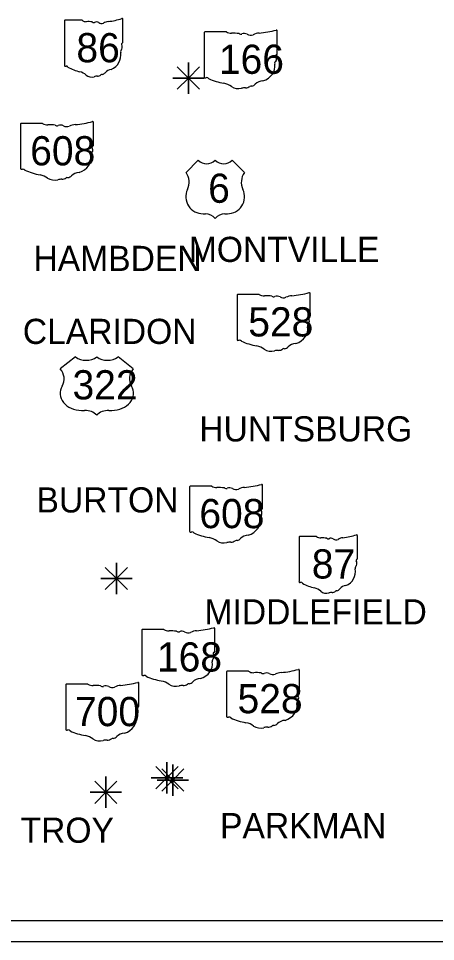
# Model space of a CAD drawing. Extents: x -1 to 48.3, y -9.3 to 22.
# Drawn here: x 5.63 to 7.62, y 14 to 18.402 of the extents above; entities that cross this region are included whole.
import ezdxf

# ---------------------------------------------------------------- set-up
doc = ezdxf.new("R2010")
doc.units = 0
for name, color, linetype in [('GM_X_County', 7, 'Continuous'), ('GM_X_County_Road', 7, 'Continuous'), ('GM_X_Minor_River_Text', 7, 'Continuous'), ('GM_X_Township', 7, 'Continuous')]:
    doc.layers.add(name, color=color, linetype=linetype)

msp = doc.modelspace()

# ---------------------------------------------------------------- linework, layer by layer
at = {"layer": 'GM_X_County'}
for p, q in [((2.1, 14.1), (8.9, 14.1)), ((2, 14), (9, 14))]:
    msp.add_line(p, q, dxfattribs=at)
at = {"layer": 'GM_X_County_Road'}
for p, q in [((5.8491, 18.3892), (5.8491, 18.1778)), ((5.9333, 18.3928), (5.8518, 18.3928)), ((6.1275, 18.2875), (6.1275, 18.398)), ((6.5168, 18.334), (6.5168, 18.1226)), ((6.6222, 18.3376), (6.5202, 18.3376)), ((6.8649, 18.2323), (6.8649, 18.3428)), ((6.1275, 18.2875), (6.1275, 18.2875)), ((6.8648, 18.2323), (6.8649, 18.2323)), ((5.6396, 17.8975), (5.6396, 17.6862)), ((5.745, 17.9011), (5.643, 17.9011)), ((5.9877, 17.7958), (5.9877, 17.9064)), ((5.9876, 17.7959), (5.9877, 17.7958)), ((6.6735, 17.0817), (6.6735, 16.8704)), ((6.7788, 17.0854), (6.6769, 17.0854)), ((7.0215, 16.9801), (7.0215, 17.0906)), ((7.0215, 16.9801), (7.0215, 16.9801)), ((6.4468, 16.1676), (6.4468, 15.9562)), ((6.5521, 16.1712), (6.4502, 16.1712)), ((6.7948, 16.0659), (6.7948, 16.1764)), ((6.7948, 16.0659), (6.7948, 16.0659)), ((7.2472, 15.8258), (7.2472, 15.9363)), ((6.9688, 15.9274), (6.9688, 15.7161)), ((7.0531, 15.9311), (6.9715, 15.9311)), ((7.2472, 15.8258), (7.2472, 15.8258)), ((6.2184, 15.4839), (6.2184, 15.2726)), ((6.3237, 15.4875), (6.2218, 15.4875)), ((6.5664, 15.3822), (6.5664, 15.4928)), ((6.5664, 15.3823), (6.5664, 15.3822)), ((6.6224, 15.285), (6.6224, 15.0737)), ((6.7277, 15.2886), (6.6258, 15.2886)), ((6.9704, 15.1833), (6.9704, 15.2939)), ((6.204, 15.1217), (6.204, 15.2323)), ((5.8559, 15.2234), (5.8559, 15.0121)), ((5.9613, 15.227), (5.8593, 15.227)), ((6.9704, 15.1834), (6.9704, 15.1833)), ((6.2039, 15.1217), (6.204, 15.1217))]:
    msp.add_line(p, q, dxfattribs=at)
for centre, radius, start, end in [((6.0283, 18.6809), 0.2953, 275.8445, 288.9065), ((6.1244, 18.3985), 0.0031, 351.8621, 97.738), ((5.8523, 18.3896), 0.00323, 98.1301, 188.1301), ((5.9528, 18.4173), 0.0313, 231.6195, 271.1119), ((5.9631, 18.2742), 0.1123, 80.4867, 94.9883), ((5.9886, 18.3907), 0.00903, 219.7921, 297.1024), ((6.0019, 18.3663), 0.0188, 54.4667, 119.1411), ((6.0261, 18.3998), 0.0226, 233.8562, 294.8282), ((6.066, 18.3283), 0.0594, 97.3462, 120.7689), ((6.1268, 18.2794), 0.0048, 107.944, 210.337), ((6.0963, 18.2654), 0.0288, 340.033, 23.6496), ((6.1242, 18.2871), 0.00332, 289.6038, 7.7341), ((6.0449, 18.2272), 0.0739, 292.3089, 8.9858), ((6.1386, 18.2412), 0.021, 136.8065, 186.9296), ((5.8523, 18.1774), 0.00325, 171.9584, 258.3066), ((5.8528, 18.199), 0.0248, 267.339, 280.6039), ((5.8579, 18.1656), 0.00895, 29.7484, 93.2717), ((5.9709, 18.3555), 0.2132, 240.4129, 257.1985), ((5.9073, 18.0829), 0.0667, 47.1842, 75.836), ((6.0275, 18.1283), 0.00635, 65.7517, 132.6484), ((6.0247, 18.1574), 0.0239, 282.8732, 323.2771), ((6.076, 18.1185), 0.0404, 94.4031, 142.5768), ((5.9795, 18.1646), 0.0423, 230.7004, 286.2918), ((6.004, 18.0915), 0.0348, 85.6951, 111.2099), ((6.007, 18.1488), 0.0226, 268.777, 315.5493), ((7.1481, 16.2192), 0.2953, 275.8445, 288.9065), ((7.2441, 15.9368), 0.0031, 351.8621, 97.738), ((6.972, 15.9279), 0.00323, 98.1301, 188.1301), ((7.0725, 15.9556), 0.0313, 231.6195, 271.1119), ((7.0829, 15.8124), 0.1123, 80.4867, 94.9883), ((7.1084, 15.929), 0.00903, 219.7921, 297.1024), ((7.1216, 15.9046), 0.0188, 54.4667, 119.1411), ((7.1458, 15.9381), 0.0226, 233.8562, 294.8282), ((7.1857, 15.8665), 0.0594, 97.3462, 120.7689), ((7.2465, 15.8176), 0.0048, 107.944, 210.337), ((7.216, 15.8037), 0.0288, 340.033, 23.6496), ((7.2439, 15.8253), 0.00332, 289.6038, 7.7341), ((7.1646, 15.7654), 0.0739, 292.3089, 8.9858), ((7.2583, 15.7795), 0.021, 136.8065, 186.9296), ((6.972, 15.7156), 0.00325, 171.9584, 258.3066), ((6.9725, 15.7373), 0.0248, 267.339, 280.6039), ((6.9776, 15.7039), 0.00895, 29.7484, 93.2717), ((7.0906, 15.8938), 0.2132, 240.4129, 257.1985), ((7.0271, 15.6212), 0.0667, 47.1842, 75.836), ((7.0992, 15.7029), 0.0423, 230.7004, 286.2918), ((7.1268, 15.687), 0.0226, 268.777, 315.5493), ((7.1472, 15.6666), 0.00635, 65.7517, 132.6484), ((7.1445, 15.6956), 0.0239, 282.8732, 323.2771), ((7.1957, 15.6568), 0.0404, 94.4031, 142.5768), ((7.1237, 15.6298), 0.0348, 85.6951, 111.2099)]:
    msp.add_arc(centre, radius, start, end, dxfattribs=at)
for centre, major_axis, start_param, end_param in [((6.5208, 18.3344), (0.00403, 0), 1.712693, 3.28349), ((6.6464, 18.3621), (0.0391, 0), 4.042523, 4.731795), ((6.6594, 18.2189), (0.1404, 0), 1.404758, 1.657858), ((6.6913, 18.3355), (0.0113, 0), 3.836095, 5.185415), ((6.7078, 18.3111), (0.0235, 0), 0.950623, 2.079405), ((6.7381, 18.3446), (0.0282, 0), 4.081561, 5.145723), ((6.788, 18.273), (0.0743, 0), 1.699011, 2.107814), ((6.7409, 18.6257), (0.3691, 0), 4.814394, 5.042369), ((6.861, 18.3433), (0.00387, 0), 6.141152, 7.989035), ((6.864, 18.2242), (0.006, 0), 1.883978, 3.671073), ((6.8607, 18.2318), (0.00415, 0), 5.05454, 6.418171), ((6.7616, 18.172), (0.0923, 0), 5.101752, 6.440018), ((6.8787, 18.186), (0.0262, 0), 2.387724, 3.262537), ((6.8258, 18.2102), (0.036, 0), 5.934695, 6.695948), ((6.5208, 18.1222), (0.00407, 0), 3.00124, 4.508301), ((6.5215, 18.1438), (0.031, 0), 4.665946, 4.897461), ((6.5278, 18.1104), (0.0112, 0), 0.519207, 1.627899), ((6.6691, 18.3003), (0.2665, 0), 4.195997, 4.488961), ((6.5897, 18.0277), (0.0834, 0), 0.823519, 1.323587), ((6.8005, 18.0633), (0.0506, 0), 1.647645, 2.488434), ((6.6799, 18.1094), (0.0529, 0), 4.026481, 4.996735), ((6.7104, 18.0363), (0.0435, 0), 1.495662, 1.94098), ((6.7143, 18.0936), (0.0282, 0), 4.691044, 5.507374), ((6.7398, 18.0731), (0.00794, 0), 1.147584, 2.315152), ((6.7364, 18.1021), (0.0298, 0), 4.937069, 5.64225), ((5.6436, 17.8979), (0.00403, 0), 1.712693, 3.28349), ((5.7692, 17.9257), (0.0391, 0), 4.042523, 4.731795), ((5.7822, 17.7825), (0.1404, 0), 1.404758, 1.657858), ((5.8141, 17.899), (0.0113, 0), 3.836095, 5.185415), ((5.8306, 17.8746), (0.0235, 0), 0.950623, 2.079405), ((5.8609, 17.9081), (0.0282, 0), 4.081561, 5.145723), ((5.9108, 17.8366), (0.0743, 0), 1.699011, 2.107814), ((5.8637, 18.1892), (0.3691, 0), 4.814394, 5.042369), ((5.9838, 17.9068), (0.00387, 0), 6.141152, 7.989035), ((5.9868, 17.7877), (0.006, 0), 1.883978, 3.671073), ((5.9486, 17.7737), (0.036, 0), 5.934695, 6.695948), ((5.9835, 17.7954), (0.00415, 0), 5.05454, 6.418171), ((5.8844, 17.7355), (0.0923, 0), 5.101752, 6.440018), ((6.0015, 17.7496), (0.0262, 0), 2.387724, 3.262537), ((5.6436, 17.6857), (0.00407, 0), 3.00124, 4.508301), ((5.6443, 17.7073), (0.031, 0), 4.665946, 4.897461), ((5.6506, 17.674), (0.0112, 0), 0.519207, 1.627899), ((5.7919, 17.8638), (0.2665, 0), 4.195997, 4.488961), ((5.7125, 17.5912), (0.0834, 0), 0.823519, 1.323587), ((5.8592, 17.6657), (0.0298, 0), 4.937069, 5.64225), ((5.9233, 17.6268), (0.0506, 0), 1.647645, 2.488434), ((5.8027, 17.6729), (0.0529, 0), 4.026481, 4.996735), ((5.8332, 17.5999), (0.0435, 0), 1.495662, 1.94098), ((5.8371, 17.6571), (0.0282, 0), 4.691044, 5.507374), ((5.8626, 17.6366), (0.00794, 0), 1.147584, 2.315152), ((6.6775, 17.0822), (0.00403, 0), 1.712693, 3.28349), ((6.8031, 17.1099), (0.0391, 0), 4.042523, 4.731795), ((6.8161, 16.9667), (0.1404, 0), 1.404758, 1.657858), ((6.8645, 17.0588), (0.0235, 0), 0.950623, 2.079405), ((6.9446, 17.0208), (0.0743, 0), 1.699011, 2.107814), ((6.8975, 17.3735), (0.3691, 0), 4.814394, 5.042369), ((7.0177, 17.0911), (0.00387, 0), 6.141152, 7.989035), ((6.8479, 17.0833), (0.0113, 0), 3.836095, 5.185415), ((6.8948, 17.0923), (0.0282, 0), 4.081561, 5.145723), ((7.0354, 16.9338), (0.0262, 0), 2.387724, 3.262537), ((7.0206, 16.9719), (0.006, 0), 1.883978, 3.671073), ((6.9825, 16.958), (0.036, 0), 5.934695, 6.695948), ((7.0174, 16.9796), (0.00415, 0), 5.05454, 6.418171), ((6.9182, 16.9197), (0.0923, 0), 5.101752, 6.440018), ((6.6775, 16.8699), (0.00407, 0), 3.00124, 4.508301), ((6.6781, 16.8916), (0.031, 0), 4.665946, 4.897461), ((6.6845, 16.8582), (0.0112, 0), 0.519207, 1.627899), ((6.8258, 17.0481), (0.2665, 0), 4.195997, 4.488961), ((6.7463, 16.7755), (0.0834, 0), 0.823519, 1.323587), ((6.8365, 16.8572), (0.0529, 0), 4.026481, 4.996735), ((6.8671, 16.7841), (0.0435, 0), 1.495662, 1.94098), ((6.871, 16.8413), (0.0282, 0), 4.691044, 5.507374), ((6.8965, 16.8209), (0.00794, 0), 1.147584, 2.315152), ((6.8931, 16.8499), (0.0298, 0), 4.937069, 5.64225), ((6.9571, 16.8111), (0.0506, 0), 1.647645, 2.488434), ((6.4508, 16.168), (0.00403, 0), 1.712693, 3.28349), ((6.5764, 16.1957), (0.0391, 0), 4.042523, 4.731795), ((6.5894, 16.0525), (0.1404, 0), 1.404758, 1.657858), ((6.6212, 16.1691), (0.0113, 0), 3.836095, 5.185415), ((6.6378, 16.1447), (0.0235, 0), 0.950623, 2.079405), ((6.6681, 16.1782), (0.0282, 0), 4.081561, 5.145723), ((6.7179, 16.1066), (0.0743, 0), 1.699011, 2.107814), ((6.6708, 16.4593), (0.3691, 0), 4.814394, 5.042369), ((6.791, 16.1769), (0.00387, 0), 6.141152, 7.989035), ((6.7907, 16.0654), (0.00415, 0), 5.05454, 6.418171), ((6.8087, 16.0196), (0.0262, 0), 2.387724, 3.262537), ((6.7939, 16.0578), (0.006, 0), 1.883978, 3.671073), ((6.7558, 16.0438), (0.036, 0), 5.934695, 6.695948), ((6.6915, 16.0055), (0.0923, 0), 5.101752, 6.440018), ((6.4508, 15.9558), (0.00407, 0), 3.00124, 4.508301), ((6.4514, 15.9774), (0.031, 0), 4.665946, 4.897461), ((6.4578, 15.944), (0.0112, 0), 0.519207, 1.627899), ((6.5991, 16.1339), (0.2665, 0), 4.195997, 4.488961), ((6.7304, 15.8969), (0.0506, 0), 1.647645, 2.488434), ((6.5196, 15.8613), (0.0834, 0), 0.823519, 1.323587), ((6.6098, 15.943), (0.0529, 0), 4.026481, 4.996735), ((6.6404, 15.8699), (0.0435, 0), 1.495662, 1.94098), ((6.6443, 15.9272), (0.0282, 0), 4.691044, 5.507374), ((6.6698, 15.9067), (0.00794, 0), 1.147584, 2.315152), ((6.6664, 15.9357), (0.0298, 0), 4.937069, 5.64225), ((6.4424, 15.7757), (0.3691, 0), 4.814394, 5.042369), ((6.5625, 15.4932), (0.00387, 0), 6.141152, 7.989035), ((6.2224, 15.4844), (0.00403, 0), 1.712693, 3.28349), ((6.348, 15.5121), (0.0391, 0), 4.042523, 4.731795), ((6.361, 15.3689), (0.1404, 0), 1.404758, 1.657858), ((6.3928, 15.4855), (0.0113, 0), 3.836095, 5.185415), ((6.4094, 15.461), (0.0235, 0), 0.950623, 2.079405), ((6.4397, 15.4945), (0.0282, 0), 4.081561, 5.145723), ((6.4895, 15.423), (0.0743, 0), 1.699011, 2.107814), ((6.5655, 15.3741), (0.006, 0), 1.883978, 3.671073), ((6.5274, 15.3601), (0.036, 0), 5.934695, 6.695948), ((6.5623, 15.3818), (0.00415, 0), 5.05454, 6.418171), ((6.4631, 15.3219), (0.0923, 0), 5.101752, 6.440018), ((6.5803, 15.336), (0.0262, 0), 2.387724, 3.262537), ((6.6264, 15.2855), (0.00403, 0), 1.712693, 3.28349), ((6.752, 15.3132), (0.0391, 0), 4.042523, 4.731795), ((6.765, 15.17), (0.1404, 0), 1.404758, 1.657858), ((6.7969, 15.2866), (0.0113, 0), 3.836095, 5.185415), ((6.8134, 15.2621), (0.0235, 0), 0.950623, 2.079405), ((6.8437, 15.2956), (0.0282, 0), 4.081561, 5.145723), ((6.8935, 15.2241), (0.0743, 0), 1.699011, 2.107814), ((6.8464, 15.5768), (0.3691, 0), 4.814394, 5.042369), ((6.9666, 15.2943), (0.00387, 0), 6.141152, 7.989035), ((6.08, 15.5151), (0.3691, 0), 4.814394, 5.042369), ((6.2001, 15.2327), (0.00387, 0), 6.141152, 7.989035), ((6.2224, 15.2721), (0.00407, 0), 3.00124, 4.508301), ((6.223, 15.2937), (0.031, 0), 4.665946, 4.897461), ((6.2294, 15.2604), (0.0112, 0), 0.519207, 1.627899), ((6.3707, 15.4503), (0.2665, 0), 4.195997, 4.488961), ((6.2912, 15.1776), (0.0834, 0), 0.823519, 1.323587), ((6.4414, 15.2231), (0.00794, 0), 1.147584, 2.315152), ((6.438, 15.2521), (0.0298, 0), 4.937069, 5.64225), ((6.502, 15.2133), (0.0506, 0), 1.647645, 2.488434), ((5.8599, 15.2238), (0.00403, 0), 1.712693, 3.28349), ((5.9855, 15.2516), (0.0391, 0), 4.042523, 4.731795), ((5.9985, 15.1084), (0.1404, 0), 1.404758, 1.657858), ((6.0304, 15.2249), (0.0113, 0), 3.836095, 5.185415), ((6.0469, 15.2005), (0.0235, 0), 0.950623, 2.079405), ((6.0772, 15.234), (0.0282, 0), 4.081561, 5.145723), ((6.1271, 15.1625), (0.0743, 0), 1.699011, 2.107814), ((6.3814, 15.2593), (0.0529, 0), 4.026481, 4.996735), ((6.412, 15.1863), (0.0435, 0), 1.495662, 1.94098), ((6.4159, 15.2435), (0.0282, 0), 4.691044, 5.507374), ((6.9843, 15.1371), (0.0262, 0), 2.387724, 3.262537), ((6.9695, 15.1752), (0.006, 0), 1.883978, 3.671073), ((6.9314, 15.1612), (0.036, 0), 5.934695, 6.695948), ((6.9663, 15.1829), (0.00415, 0), 5.05454, 6.418171), ((6.2031, 15.1136), (0.006, 0), 1.883978, 3.671073), ((6.1649, 15.0996), (0.036, 0), 5.934695, 6.695948), ((6.1998, 15.1213), (0.00415, 0), 5.05454, 6.418171), ((6.8671, 15.123), (0.0923, 0), 5.101752, 6.440018), ((6.1007, 15.0614), (0.0923, 0), 5.101752, 6.440018), ((6.2178, 15.0754), (0.0262, 0), 2.387724, 3.262537), ((6.6264, 15.0732), (0.00407, 0), 3.00124, 4.508301), ((6.627, 15.0948), (0.031, 0), 4.665946, 4.897461), ((6.6334, 15.0615), (0.0112, 0), 0.519207, 1.627899), ((6.7747, 15.2514), (0.2665, 0), 4.195997, 4.488961), ((6.906, 15.0144), (0.0506, 0), 1.647645, 2.488434), ((5.8599, 15.0116), (0.00407, 0), 3.00124, 4.508301), ((6.6952, 14.9787), (0.0834, 0), 0.823519, 1.323587), ((6.7854, 15.0604), (0.0529, 0), 4.026481, 4.996735), ((6.816, 14.9874), (0.0435, 0), 1.495662, 1.94098), ((6.8199, 15.0446), (0.0282, 0), 4.691044, 5.507374), ((6.8454, 15.0242), (0.00794, 0), 1.147584, 2.315152), ((6.842, 15.0532), (0.0298, 0), 4.937069, 5.64225), ((5.8606, 15.0332), (0.031, 0), 4.665946, 4.897461), ((5.8669, 14.9999), (0.0112, 0), 0.519207, 1.627899), ((6.0082, 15.1897), (0.2665, 0), 4.195997, 4.488961), ((5.9288, 14.9171), (0.0834, 0), 0.823519, 1.323587), ((6.019, 14.9988), (0.0529, 0), 4.026481, 4.996735), ((6.0534, 14.983), (0.0282, 0), 4.691044, 5.507374), ((6.0789, 14.9625), (0.00794, 0), 1.147584, 2.315152), ((6.0755, 14.9916), (0.0298, 0), 4.937069, 5.64225), ((6.1396, 14.9527), (0.0506, 0), 1.647645, 2.488434), ((6.0495, 14.9258), (0.0435, 0), 1.495662, 1.94098)]:
    msp.add_ellipse(centre, major_axis=major_axis, ratio=0.8, start_param=start_param, end_param=end_param, dxfattribs=at)
at = {"layer": 'GM_X_Minor_River_Text'}
for p, q in [((6.4877, 17.7256), (6.4297, 17.6676)), ((6.7081, 17.6676), (6.6501, 17.7256)), ((6.5109, 17.4704), (6.5225, 17.4704)), ((6.6153, 17.4704), (6.6269, 17.4704)), ((5.9021, 16.7882), (5.8295, 16.7302)), ((6.1776, 16.7302), (6.1051, 16.7882)), ((5.9311, 16.5329), (5.9456, 16.5329)), ((6.0616, 16.5329), (6.0761, 16.5329))]:
    msp.add_line(p, q, dxfattribs=at)
for centre, radius, start, end in [((6.5283, 17.7671), 0.058, 225.573, 314.427), ((6.6095, 17.7671), 0.058, 225.573, 314.427), ((6.3631, 17.621), 0.0812, 334.5471, 35.0009), ((6.7746, 17.621), 0.0812, 144.9991, 205.4529), ((6.51, 17.5516), 0.0812, 154.8319, 270.6383), ((6.6278, 17.5516), 0.0812, 269.3617, 25.1681), ((6.5225, 17.4124), 0.058, 36.8699, 90), ((6.6153, 17.4124), 0.058, 90, 143.1301)]:
    msp.add_arc(centre, radius, start, end, dxfattribs=at)
for centre, major_axis, start_param, end_param in [((5.9528, 16.8296), (-0.0725, 0), 0.795399, 2.346194), ((6.0543, 16.8296), (-0.0725, 0), 0.795399, 2.346194), ((5.7464, 16.6836), (0.1015, 0), 5.838949, 6.894067), ((6.2607, 16.6836), (-0.1015, 0), 5.672304, 6.727422), ((5.9299, 16.6141), (0.1015, 0), 2.702327, 4.723529), ((6.0772, 16.6141), (-0.1015, 0), 1.559657, 3.580859), ((5.9456, 16.4749), (-0.0725, 0), 3.785094, 4.712389), ((6.0616, 16.4749), (-0.0725, 0), 4.712389, 5.639684)]:
    msp.add_ellipse(centre, major_axis=major_axis, ratio=0.8, start_param=start_param, end_param=end_param, dxfattribs=at)
at = {"layer": 'GM_X_Township'}
for points in [[(6.3659, 18.1173), (6.4409, 18.1173), (6.3879, 18.1703), (6.4409, 18.1173), (6.4409, 18.1923), (6.4409, 18.1173), (6.494, 18.1703), (6.4409, 18.1173), (6.5159, 18.1173), (6.4409, 18.1173), (6.494, 18.0642), (6.4409, 18.1173), (6.4409, 18.0423), (6.4409, 18.1173), (6.3879, 18.0642), (6.4409, 18.1173)], [(6.0225, 15.731), (6.0975, 15.731), (6.0444, 15.7841), (6.0975, 15.731), (6.0975, 15.806), (6.0975, 15.731), (6.1505, 15.7841), (6.0975, 15.731), (6.1725, 15.731), (6.0975, 15.731), (6.1505, 15.678), (6.0975, 15.731), (6.0975, 15.656), (6.0975, 15.731), (6.0444, 15.678), (6.0975, 15.731)], [(6.2638, 14.7811), (6.3388, 14.7811), (6.2858, 14.8341), (6.3388, 14.7811), (6.3388, 14.8561), (6.3388, 14.7811), (6.3919, 14.8341), (6.3388, 14.7811), (6.4138, 14.7811), (6.3388, 14.7811), (6.3919, 14.728), (6.3388, 14.7811), (6.3388, 14.7061), (6.3388, 14.7811), (6.2858, 14.728), (6.3388, 14.7811)], [(6.2917, 14.7698), (6.3667, 14.7698), (6.3136, 14.8228), (6.3667, 14.7698), (6.3667, 14.8448), (6.3667, 14.7698), (6.4197, 14.8228), (6.3667, 14.7698), (6.4417, 14.7698), (6.3667, 14.7698), (6.4197, 14.7168), (6.3667, 14.7698), (6.3667, 14.6948), (6.3667, 14.7698), (6.3136, 14.7168), (6.3667, 14.7698)], [(5.9717, 14.7118), (6.0467, 14.7118), (5.9937, 14.7648), (6.0467, 14.7118), (6.0467, 14.7868), (6.0467, 14.7118), (6.0998, 14.7648), (6.0467, 14.7118), (6.1217, 14.7118), (6.0467, 14.7118), (6.0998, 14.6587), (6.0467, 14.7118), (6.0467, 14.6368), (6.0467, 14.7118), (5.9937, 14.6587), (6.0467, 14.7118)]]:
    msp.add_lwpolyline(points, close=True, dxfattribs=at)

# ---------------------------------------------------------------- texts
at = {"layer": 'GM_X_County_Road'}
for s, p in [('86', (5.9065, 18.1927)), ('166', (6.5864, 18.1375)), ('608', (5.686, 17.7011)), ('528', (6.7266, 16.8853)), ('608', (6.4932, 15.9711)), ('87', (7.0298, 15.731)), ('168', (6.2909, 15.2875)), ('528', (6.6755, 15.0886)), ('700', (5.8998, 15.027))]:
    msp.add_text(s, height=0.13922, dxfattribs=at).set_placement(p)
at = {"layer": 'GM_X_Minor_River_Text'}
for s, height, p in [('6', 0.1392, (6.5352, 17.5226)), ('322', 0.13922, (5.8879, 16.5851))]:
    msp.add_text(s, height=height, dxfattribs=at).set_placement(p)
at = {"layer": 'GM_X_Township'}
for s, p in [('MONTVILLE', (6.443, 17.2405)), ('HAMBDEN', (5.7017, 17.1974)), ('CLARIDON', (5.6507, 16.8495)), ('HUNTSBURG', (6.4929, 16.3846)), ('BURTON', (5.7161, 16.0459)), ('MIDDLEFIELD', (6.5178, 15.5121)), ('TROY', (5.6399, 14.4709)), ('PARKMAN', (6.5921, 14.4927))]:
    msp.add_text(s, height=0.12, rotation=0, dxfattribs=at).set_placement(p)

doc.saveas('drawing.dxf')
